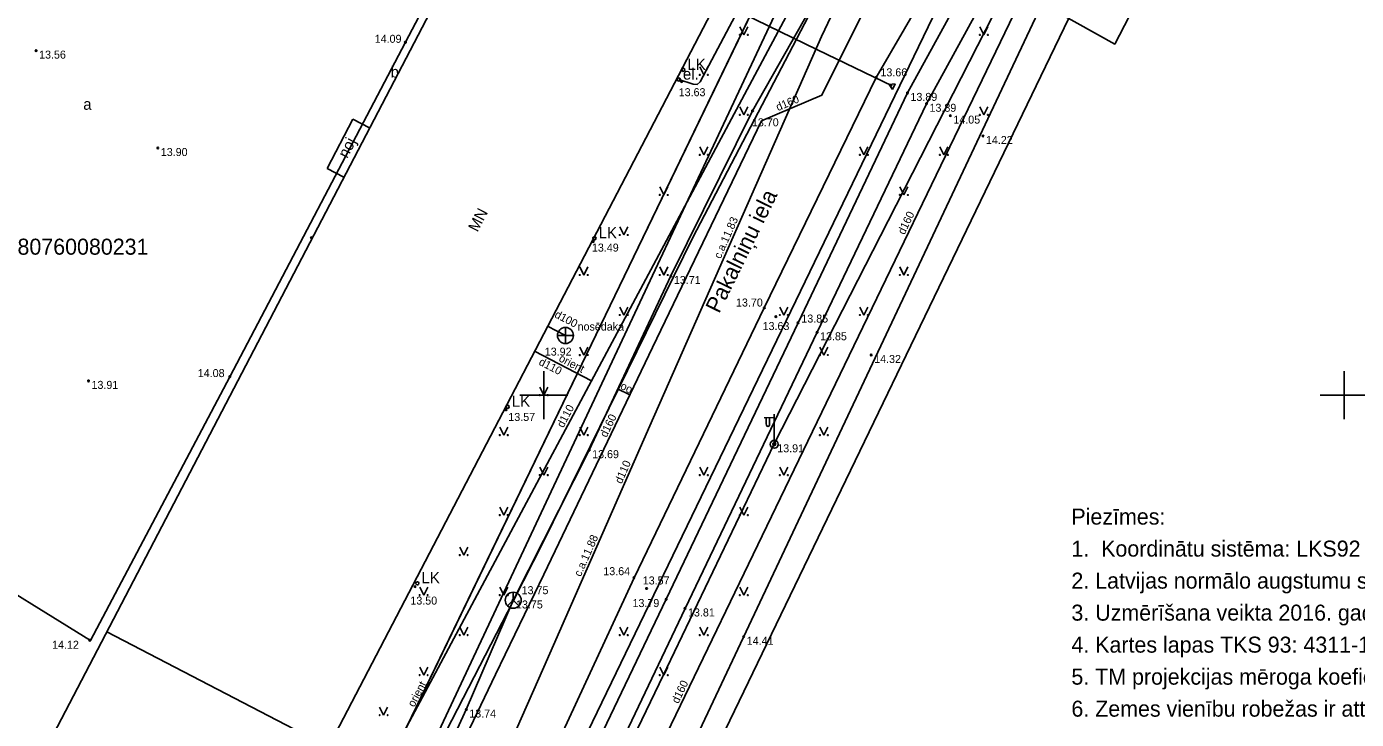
# Model space of a CAD drawing. Extents: x 503904 to 504094, y 304688 to 304960.
# Drawn here: x 503967.7 to 504050.8, y 304779.7 to 304823 of the extents above; entities that cross this region are included whole.
import ezdxf

# ---------------------------------------------------------------- set-up
doc = ezdxf.new("R2010")
doc.units = 0
for name, color, linetype in [('APGR_SARK_####_####_#', 7, 'Continuous'), ('APGS_ELEM_####_####_#', 7, 'Continuous'), ('APGS_VADP_ZSPR_####_#', 7, 'Continuous'), ('BUVE_BALK_####_####_#', 7, 'Continuous'), ('BUVE_EKAS_####_####_#', 7, 'Continuous'), ('BUVE_EKAS_RAKS_TKST_#', 7, 'Continuous'), ('CELI_CMAL_####_####_#', 7, 'Continuous'), ('CELI_CSEG_####_TKST_#', 7, 'Continuous'), ('CELI_IELA_####_TKST_#', 7, 'Continuous'), ('ELEK_ELEM_####_####_#', 7, 'Continuous'), ('ELEK_VADP_NEDR_####_#', 7, 'Continuous'), ('GAZE_VADP_VSP2_####_#', 7, 'Continuous'), ('GAZE_VADP_VSP2_TKST_#', 7, 'Continuous'), ('GEOD_ELEM_####_####_#', 7, 'Continuous'), ('LKAN_ELEM_####_####_#', 7, 'Continuous'), ('RAMI_PLAN_####_TKST_#', 7, 'Continuous'), ('RAMI_UZMR_####_####_#', 7, 'Continuous'), ('RELJ_AATZ_####_TKST_#', 7, 'Continuous'), ('RELJ_ELEM_####_####_#', 7, 'Continuous'), ('ROBZ_UZMR_####_####_#', 7, 'Continuous'), ('ROBZ_UZMR_####_TKST_#', 7, 'Continuous'), ('SAKK_ELEM_####_####_#', 7, 'Continuous'), ('SAKK_ELEM_####_TKST_#', 7, 'Continuous'), ('SAKK_IZVK_####_TKST_#', 7, 'Continuous'), ('SAKK_KKAN_####_####_#', 7, 'Continuous'), ('SAKT_VADP_KABE_####_#', 7, 'Continuous'), ('SKAN_ELEM_####_####_#', 7, 'Continuous'), ('SKAN_ELEM_PAST_TKST_#', 7, 'Continuous'), ('SKAN_VADP_PAST_####_#', 7, 'Continuous'), ('SKAN_VADP_PAST_TKST_#', 7, 'Continuous'), ('SKAN_VADP_SPDK_####_I', 7, 'Continuous'), ('SKAN_VADP_SPDK_TKST_I', 7, 'Continuous'), ('TERT_ELEM_####_####_#', 7, 'Continuous'), ('UDTK_VADP_UDEN_####_#', 7, 'Continuous'), ('UDTK_VADP_UDEN_TKST_#', 7, 'Continuous')]:
    doc.layers.add(name, color=color, linetype=linetype)

msp = doc.modelspace()

# ---------------------------------------------------------------- linework, layer by layer
at = {"layer": 'APGR_SARK_####_####_#'}
for p, q in [((504030.463, 304860.121), (503981.982, 304759.672)), ((504032.794, 304823.54), (503998.701, 304752.902))]:
    msp.add_line(p, q, dxfattribs=at)
at = {"layer": 'APGS_ELEM_####_####_#'}
for p, q in [((504014.404, 304798.589), (504013.769, 304798.584)), ((504013.904, 304798.585), (504013.904, 304798.193)), ((504014.114, 304798.587), (504014.114, 304798.193)), ((504014.404, 304796.922), (504014.404, 304798.805))]:
    msp.add_line(p, q, dxfattribs=at)
for radius in [0.25, 0.09]:
    msp.add_circle((504014.404, 304796.922), radius, dxfattribs=at)
msp.add_ellipse((504014.009, 304798.193), major_axis=(0, 0.151), ratio=0.695971, start_param=1.570796, end_param=4.712389, dxfattribs=at)
at = {"layer": 'APGS_VADP_ZSPR_####_#'}
for points in [[(504014.402, 304796.949), (504021.513, 304810.881), (504028.624, 304824.813), (504030.913, 304829.297), (504033.174, 304833.728), (504034.064, 304835.47), (504034.948, 304837.203)], [(503997.69, 304760.643), (503998.828, 304763.774), (503999.966, 304766.905), (504007.201, 304781.962), (504014.402, 304796.949)]]:
    msp.add_lwpolyline(points, dxfattribs=at)
at = {"layer": 'BUVE_BALK_####_####_#'}
for points in [[(503988.071, 304817.243), (503986.462, 304814.159)], [(503988.071, 304817.243), (503989.125, 304816.693)], [(503986.462, 304814.159), (503987.516, 304813.609)]]:
    msp.add_lwpolyline(points, dxfattribs=at)
at = {"layer": 'BUVE_EKAS_####_####_#'}
for p, q in [((504000.528, 304838.553), (503966.985, 304774.25)), ((503980.794, 304766.985), (504014.326, 304831.324)), ((503986.542, 304778.014), (503972.696, 304785.199))]:
    msp.add_line(p, q, dxfattribs=at)
at = {"layer": 'CELI_CMAL_####_####_#'}
msp.add_line((504013.046, 304817.755), (504026.066, 304840.762), dxfattribs=at)
for points in [[(503988.454, 304902.158), (503990.823, 304901.054), (503991.097, 304895.946), (503989.732, 304890.943), (503987.103, 304886.103), (503981.039, 304876.47), (503973.971, 304864.108), (503962.412, 304839.295), (503956.935, 304827.255), (503950.616, 304813.727), (503945.51, 304803.343), (503951.501, 304800.629), (503951.721, 304801.18), (503956.987, 304798.767), (503955.478, 304795.066), (503959.037, 304792.215), (503963.727, 304789.581), (503971.677, 304784.658)], [(503980.391, 304801.145), (503991.362, 304822.043), (504000.143, 304838.769)], [(503992.452, 304751.249), (503998.132, 304767.348), (504007.65, 304787.237), (504015.889, 304804.514), (504022.724, 304818.878), (504029.221, 304830.725)], [(504030.694, 304830.598), (504023.914, 304818.199), (504017.078, 304803.923), (504008.828, 304786.666), (503999.434, 304766.943), (503993.551, 304750.365)], [(503990.5, 304752.82), (503993.697, 304762.375), (503994.484, 304764.359), (503996.214, 304768.221), (504005.642, 304788.589), (504013.779, 304805.451), (504020.778, 304819.846), (504026.069, 304828.977)], [(504013.046, 304817.755), (504007.946, 304807.438), (504002.84, 304796.556), (503998.081, 304787.166), (503995.164, 304780.353), (503989.767, 304768.519), (503988.799, 304765.396), (503986.11, 304756.351)], [(503971.677, 304784.658), (503980.391, 304801.145)]]:
    msp.add_lwpolyline(points, dxfattribs=at)
at = {"layer": 'ELEK_ELEM_####_####_#'}
for points in [[(504021.782, 304819.089), (504021.581, 304819.409), (504021.956, 304819.449)], [(504021.956, 304819.449), (504021.782, 304819.089)]]:
    msp.add_lwpolyline(points, dxfattribs=at)
msp.add_circle((504008.434, 304819.711), 0.1, dxfattribs=at)
at = {"layer": 'ELEK_VADP_NEDR_####_#'}
for points in [[(504021.775, 304819.315), (504017.104, 304821.576), (504012.433, 304823.836), (504012.326, 304823.953), (504012.339, 304824.112), (504013.491, 304826.283), (504014.644, 304828.454), (504016.196, 304831.379), (504017.749, 304834.304), (504019.433, 304837.477), (504021.118, 304840.651), (504023.847, 304845.791), (504025.258, 304848.45), (504028.54, 304854.632), (504031.821, 304860.814), (504022.135, 304867.596), (504012.45, 304874.378)], [(504014.517, 304828.507), (504012.149, 304824.043), (504009.782, 304819.579), (504009.585, 304819.412), (504009.326, 304819.425), (504008.434, 304819.711)]]:
    msp.add_lwpolyline(points, dxfattribs=at)
at = {"layer": 'GAZE_VADP_VSP2_####_#'}
msp.add_lwpolyline([(504042.754, 304870.726), (504040.842, 304866.35), (504038.93, 304861.973), (504035.12, 304854.33), (504031.31, 304846.687), (504029.002, 304842.057), (504026.694, 304837.426), (504024.595, 304833.216), (504022.496, 304829.005), (504019.148, 304822.29), (504017.375, 304818.733), (504013.61, 304817.132), (504006.805, 304802.964), (504000, 304788.796), (503996.994, 304782.538), (503993.988, 304776.279), (503986.861, 304755.747)], dxfattribs=at)
at = {"layer": 'GEOD_ELEM_####_####_#'}
for p, q in [((504000, 304801.5), (504000, 304800)), ((504050, 304801.5), (504050, 304800)), ((503998.5, 304800), (504000, 304800)), ((504000, 304800), (504000, 304798.5)), ((504000, 304800), (504001.5, 304800)), ((504048.5, 304800), (504050, 304800)), ((504050, 304800), (504050, 304798.5)), ((504050, 304800), (504051.5, 304800))]:
    msp.add_line(p, q, dxfattribs=at)
at = {"layer": 'LKAN_ELEM_####_####_#'}
for centre in [(504008.717, 304820.318), (504003.169, 304809.791), (503997.749, 304799.265), (503992.105, 304788.24)]:
    msp.add_circle(centre, 0.1, dxfattribs=at)
at = {"layer": 'RAMI_UZMR_####_####_#'}
msp.add_lwpolyline([(503923.253, 304801.015), (503981.982, 304759.672), (503995.48, 304748.813), (504027.75, 304817.255), (504060.02, 304885.696), (504048.875, 304885.773), (504036.803, 304888.853), (503994.536, 304908.303), (503981.123, 304894.75), (503978.518, 304892.436), (503950.886, 304846.726), (503923.253, 304801.015)], dxfattribs=at)
at = {"layer": 'RELJ_ELEM_####_####_#'}
for centre in [(503968.288, 304821.519), (503991.362, 304822.043), (504020.778, 304819.846), (504008.62, 304819.584), (504022.724, 304818.878), (504023.914, 304818.199), (504013.046, 304817.755), (504025.406, 304817.459), (504027.44, 304816.183), (503975.891, 304815.433), (503985.486, 304809.827), (504003.088, 304809.591), (504007.946, 304807.438), (504013.779, 304805.451), (504014.502, 304804.898), (504015.889, 304804.514), (504017.078, 304803.923), (504020.458, 304802.504), (503971.562, 304800.885), (503980.391, 304801.145), (503997.64, 304799.08), (504002.84, 304796.556), (504005.642, 304788.589), (503991.954, 304788.033), (504006.424, 304787.913), (503998.081, 304787.166), (504007.65, 304787.237), (504008.828, 304786.666), (503971.641, 304784.68), (504012.496, 304784.899), (503995.164, 304780.353)]:
    msp.add_circle(centre, 0.05, dxfattribs=at)
at = {"layer": 'ROBZ_UZMR_####_####_#'}
msp.add_lwpolyline([(503923.29, 304801.044), (503978.518, 304892.436), (503981.123, 304894.75), (504030.463, 304860.121), (503981.982, 304759.672)], close=True, dxfattribs=at)
msp.add_lwpolyline([(503976.684, 304743.679), (503981.982, 304759.672), (504030.463, 304860.121), (504048.85, 304847.4), (504035.67, 304821.93), (504026.069, 304827.305), (503995.067, 304763.071), (503986.854, 304740.353)], dxfattribs=at)
at = {"layer": 'SAKK_ELEM_####_####_#'}
msp.add_line((503998.095, 304787.182), (503998.449, 304786.828), dxfattribs=at)
msp.add_lwpolyline([(503998.095, 304787.682), (503998.095, 304787.182), (503997.741, 304786.828)], dxfattribs=at)
msp.add_circle((503998.095, 304787.182), 0.5, dxfattribs=at)
at = {"layer": 'SAKK_IZVK_####_TKST_#'}
msp.add_line((504004.653, 304800.369), (504005.344, 304800.035), dxfattribs=at)
at = {"layer": 'SAKK_KKAN_####_####_#'}
msp.add_lwpolyline([(504039.007, 304870.064), (504036.678, 304863.872), (504034.349, 304857.68), (504031.408, 304852.312), (504030.269, 304850.237), (504027.088, 304844.191), (504022.232, 304834.693), (504020.138, 304830.591), (504009.306, 304809.848), (504000, 304790.89), (503998.089, 304787.127), (503992.169, 304775.655), (503986.248, 304764.183), (503984.196, 304757.891)], dxfattribs=at)
at = {"layer": 'SAKT_VADP_KABE_####_#'}
msp.add_lwpolyline([(503984.36, 304757.759), (503986.696, 304764.614), (504000.633, 304794.323), (504014.571, 304824.033), (504017.941, 304829.488), (504018.377, 304830.312), (504025.72, 304844.17), (504033.498, 304858.852), (504046.129, 304856.235)], dxfattribs=at)
at = {"layer": 'SKAN_ELEM_####_####_#'}
for p, q in [((504001.356, 304803.22), (504001.356, 304804.22)), ((504000.856, 304803.72), (504001.856, 304803.72))]:
    msp.add_line(p, q, dxfattribs=at)
msp.add_circle((504001.356, 304803.72), 0.5, dxfattribs=at)
at = {"layer": 'SKAN_VADP_PAST_####_#'}
msp.add_lwpolyline([(504001.356, 304803.72), (504000.242, 304804.301)], dxfattribs=at)
at = {"layer": 'SKAN_VADP_SPDK_####_I'}
msp.add_lwpolyline([(503989.264, 304753.814), (503995.932, 304773.743), (504000, 304782.989), (504006.638, 304798.076), (504017.345, 304822.408), (504018.739, 304825.349), (504022.372, 304833.011), (504023.783, 304835.985)], dxfattribs=at)
at = {"layer": 'TERT_ELEM_####_####_#'}
for p, q in [((504012.25, 304823), (504012.5, 304822.5)), ((504012.5, 304822.5), (504012.75, 304823)), ((504027.25, 304823), (504027.5, 304822.5)), ((504027.5, 304822.5), (504027.75, 304823)), ((504009.75, 304820.5), (504010, 304820)), ((504010, 304820), (504010.25, 304820.5)), ((504012.25, 304818), (504012.5, 304817.5)), ((504012.5, 304817.5), (504012.75, 304818)), ((504027.25, 304818), (504027.5, 304817.5)), ((504027.5, 304817.5), (504027.75, 304818)), ((504009.75, 304815.5), (504010, 304815)), ((504010, 304815), (504010.25, 304815.5)), ((504019.75, 304815.5), (504020, 304815)), ((504020, 304815), (504020.25, 304815.5)), ((504024.75, 304815.5), (504025, 304815)), ((504025, 304815), (504025.25, 304815.5)), ((504007.25, 304813), (504007.5, 304812.5)), ((504007.5, 304812.5), (504007.75, 304813)), ((504022.25, 304813), (504022.5, 304812.5)), ((504022.5, 304812.5), (504022.75, 304813)), ((504004.75, 304810.5), (504005, 304810)), ((504005, 304810), (504005.25, 304810.5)), ((504002.25, 304808), (504002.5, 304807.5)), ((504002.5, 304807.5), (504002.75, 304808)), ((504007.25, 304808), (504007.5, 304807.5)), ((504007.5, 304807.5), (504007.75, 304808)), ((504022.25, 304808), (504022.5, 304807.5)), ((504022.5, 304807.5), (504022.75, 304808)), ((504004.75, 304805.5), (504005, 304805)), ((504005, 304805), (504005.25, 304805.5)), ((504014.75, 304805.5), (504015, 304805)), ((504015, 304805), (504015.25, 304805.5)), ((504019.75, 304805.5), (504020, 304805)), ((504020, 304805), (504020.25, 304805.5)), ((504002.25, 304803), (504002.5, 304802.5)), ((504002.5, 304802.5), (504002.75, 304803)), ((504017.25, 304803), (504017.5, 304802.5)), ((504017.5, 304802.5), (504017.75, 304803)), ((503999.75, 304800.5), (504000, 304800)), ((504000, 304800), (504000.25, 304800.5)), ((503997.25, 304798), (503997.5, 304797.5)), ((503997.5, 304797.5), (503997.75, 304798)), ((504002.25, 304798), (504002.5, 304797.5)), ((504002.5, 304797.5), (504002.75, 304798)), ((504017.25, 304798), (504017.5, 304797.5)), ((504017.5, 304797.5), (504017.75, 304798)), ((503999.75, 304795.5), (504000, 304795)), ((504000, 304795), (504000.25, 304795.5)), ((504009.75, 304795.5), (504010, 304795)), ((504010, 304795), (504010.25, 304795.5)), ((504014.75, 304795.5), (504015, 304795)), ((504015, 304795), (504015.25, 304795.5)), ((503997.25, 304793), (503997.5, 304792.5)), ((503997.5, 304792.5), (503997.75, 304793)), ((504012.25, 304793), (504012.5, 304792.5)), ((504012.5, 304792.5), (504012.75, 304793)), ((503994.75, 304790.5), (503995, 304790)), ((503995, 304790), (503995.25, 304790.5)), ((503992.25, 304788), (503992.5, 304787.5)), ((503992.5, 304787.5), (503992.75, 304788)), ((503997.25, 304788), (503997.5, 304787.5)), ((503997.5, 304787.5), (503997.75, 304788)), ((504012.25, 304788), (504012.5, 304787.5)), ((504012.5, 304787.5), (504012.75, 304788)), ((503994.75, 304785.5), (503995, 304785)), ((503995, 304785), (503995.25, 304785.5)), ((504004.75, 304785.5), (504005, 304785)), ((504005, 304785), (504005.25, 304785.5)), ((504009.75, 304785.5), (504010, 304785)), ((504010, 304785), (504010.25, 304785.5)), ((503992.25, 304783), (503992.5, 304782.5)), ((503992.5, 304782.5), (503992.75, 304783)), ((504007.25, 304783), (504007.5, 304782.5)), ((504007.5, 304782.5), (504007.75, 304783)), ((503989.75, 304780.5), (503990, 304780)), ((503990, 304780), (503990.25, 304780.5))]:
    msp.add_line(p, q, dxfattribs=at)
for centre, radius in [((504012.25, 304822.5), 0.028), ((504012.75, 304822.5), 0.0263), ((504027.25, 304822.5), 0.028), ((504027.75, 304822.5), 0.0263), ((504009.75, 304820), 0.028), ((504010.25, 304820), 0.0263), ((504012.25, 304817.5), 0.028), ((504012.75, 304817.5), 0.0263), ((504027.25, 304817.5), 0.028), ((504027.75, 304817.5), 0.0263), ((504009.75, 304815), 0.028), ((504010.25, 304815), 0.0263), ((504019.75, 304815), 0.028), ((504020.25, 304815), 0.0263), ((504024.75, 304815), 0.028), ((504025.25, 304815), 0.0263), ((504007.25, 304812.5), 0.028), ((504007.75, 304812.5), 0.0263), ((504022.25, 304812.5), 0.028), ((504022.75, 304812.5), 0.0263), ((504004.75, 304810), 0.028), ((504005.25, 304810), 0.0263), ((504002.25, 304807.5), 0.028), ((504002.75, 304807.5), 0.0263), ((504007.25, 304807.5), 0.028), ((504007.75, 304807.5), 0.0263), ((504022.25, 304807.5), 0.028), ((504022.75, 304807.5), 0.0263), ((504004.75, 304805), 0.028), ((504005.25, 304805), 0.0263), ((504014.75, 304805), 0.028), ((504015.25, 304805), 0.0263), ((504019.75, 304805), 0.028), ((504020.25, 304805), 0.0263), ((504002.25, 304802.5), 0.028), ((504002.75, 304802.5), 0.0263), ((504017.25, 304802.5), 0.028), ((504017.75, 304802.5), 0.0263), ((503999.75, 304800), 0.028), ((504000.25, 304800), 0.0263), ((503997.25, 304797.5), 0.028), ((503997.75, 304797.5), 0.0263), ((504002.25, 304797.5), 0.028), ((504002.75, 304797.5), 0.0263), ((504017.25, 304797.5), 0.028), ((504017.75, 304797.5), 0.0263), ((503999.75, 304795), 0.028), ((504000.25, 304795), 0.0263), ((504009.75, 304795), 0.028), ((504010.25, 304795), 0.0263), ((504014.75, 304795), 0.028), ((504015.25, 304795), 0.0263), ((503997.25, 304792.5), 0.028), ((503997.75, 304792.5), 0.0263), ((504012.25, 304792.5), 0.028), ((504012.75, 304792.5), 0.0263), ((503994.75, 304790), 0.028), ((503995.25, 304790), 0.0263), ((503992.25, 304787.5), 0.028), ((503992.75, 304787.5), 0.0263), ((503997.25, 304787.5), 0.028), ((503997.75, 304787.5), 0.0263), ((504012.25, 304787.5), 0.028), ((504012.75, 304787.5), 0.0263), ((503994.75, 304785), 0.028), ((503995.25, 304785), 0.0263), ((504004.75, 304785), 0.028), ((504005.25, 304785), 0.0263), ((504009.75, 304785), 0.028), ((504010.25, 304785), 0.0263), ((503992.25, 304782.5), 0.028), ((503992.75, 304782.5), 0.0263), ((504007.25, 304782.5), 0.028), ((504007.75, 304782.5), 0.0263), ((503989.75, 304780), 0.028), ((503990.25, 304780), 0.0263)]:
    msp.add_circle(centre, radius, dxfattribs=at)
at = {"layer": 'UDTK_VADP_UDEN_####_#'}
for points in [[(504052.599, 304884.688), (504054.563, 304874.709), (504047.684, 304860.837), (504037.414, 304840.144), (504031.385, 304827.996), (504014.788, 304793.579), (504000, 304762.914), (503998.944, 304760.723), (503997.887, 304758.532), (503994.035, 304750.096), (503993.994, 304750.008)], [(504035.876, 304862.497), (503981.246, 304760.191)], [(504002.977, 304800.887), (503999.427, 304802.737)]]:
    msp.add_lwpolyline(points, dxfattribs=at)

# ---------------------------------------------------------------- texts
at = {"layer": 'BUVE_EKAS_RAKS_TKST_#'}
for s, rotation, p in [('noj', 62.45166, (503987.725, 304814.745)), ('MN', 62.47252, (503995.862, 304810.141))]:
    msp.add_text(s, height=0.7, rotation=rotation, dxfattribs=at).set_placement(p)
at = {"layer": 'CELI_CSEG_####_TKST_#'}
for s, p in [('b', (503990.431, 304819.837)), ('a', (503971.232, 304817.823))]:
    msp.add_text(s, height=0.7, dxfattribs=at).set_placement(p)
at = {"layer": 'CELI_IELA_####_TKST_#'}
msp.add_text('Pakalniņu iela', height=1, rotation=63.86421, dxfattribs=at).set_placement((504010.957, 304805.048))
at = {"layer": 'ELEK_ELEM_####_####_#'}
msp.add_text(' el.', height=0.7, dxfattribs=at).set_placement((504008.434, 304819.711))
at = {"layer": 'GAZE_VADP_VSP2_TKST_#'}
for rotation, p in [(23.03677, (504014.636, 304817.731)), (64.34467, (504003.925, 304797.314))]:
    msp.add_text('d160', height=0.5, rotation=rotation, dxfattribs=at).set_placement(p)
at = {"layer": 'LKAN_ELEM_####_####_#'}
for p in [(504008.717, 304820.318), (504003.169, 304809.791), (503997.749, 304799.265), (503992.105, 304788.24)]:
    msp.add_text(' LK', height=0.7, dxfattribs=at).set_placement(p)
at = {"layer": 'RAMI_PLAN_####_TKST_#'}
for s, p in [('Piezīmes:', (504032.965, 304791.905)), ('1.  Koordinātu sistēma: LKS92 TM', (504032.965, 304789.905)), ('2. Latvijas normālo augstumu sistēma (LAS-2000,5)', (504032.965, 304787.905)), ('3. Uzmērīšana veikta 2016. gada 9. jūnijā', (504032.965, 304785.905)), ('4. Kartes lapas TKS 93: 4311-11-55.3-807600, 4311-11-54.4-807600', (504032.965, 304783.905)), ('5. TM projekcijas mēroga koeficents 0.999600', (504032.965, 304781.905)), ('6. Zemes vienību robežas ir attēlotas atbilstoši zemes ', (504032.965, 304779.905))]:
    msp.add_text(s, height=1, rotation=360, dxfattribs=at).set_placement(p)
at = {"layer": 'RELJ_AATZ_####_TKST_#'}
for s, p in [(' 14.09', (503989.255, 304822.008)), (' 13.56', (503968.288, 304821.019)), (' 13.66', (504020.848, 304819.912)), (' 13.63', (504008.245, 304818.67)), (' 13.89', (504022.724, 304818.378)), (' 13.89', (504023.914, 304817.699)), (' 14.05', (504025.406, 304816.959)), (' 13.70', (504012.819, 304816.79)), (' 14.22', (504027.44, 304815.683)), (' 13.90', (503975.891, 304814.933)), (' 13.49', (504002.825, 304808.963)), (' 13.71', (504007.946, 304806.938)), (' 13.70', (504011.825, 304805.53)), (' 13.85', (504015.907, 304804.528)), (' 13.63', (504013.488, 304804.06)), (' 13.85', (504017.078, 304803.423)), (' 14.32', (504020.458, 304802.004)), (' 14.08', (503978.203, 304801.122)), (' 13.91', (503971.562, 304800.385)), (' 13.57', (503997.602, 304798.381)), (' 13.91', (504014.404, 304796.422)), (' 13.69', (504002.84, 304796.056)), (' 13.64', (504003.536, 304788.746)), (' 13.57', (504006, 304788.166)), (' 13.50', (503991.484, 304786.909)), (' 13.75', (503998.081, 304786.666)), (' 13.79', (504005.36, 304786.753)), (' 13.81', (504008.828, 304786.166)), (' 14.12', (503969.101, 304784.149)), (' 14.41', (504012.496, 304784.399)), (' 13.74', (503995.164, 304779.853))]:
    msp.add_text(s, height=0.5, dxfattribs=at).set_placement(p)
at = {"layer": 'ROBZ_UZMR_####_TKST_#'}
msp.add_text('80760080231', height=1, dxfattribs=at).set_placement((503967.125, 304808.769))
at = {"layer": 'SAKK_ELEM_####_TKST_#'}
msp.add_text('13.75', height=0.5, dxfattribs=at).set_placement((503998.619, 304787.558))
at = {"layer": 'SAKK_IZVK_####_TKST_#'}
msp.add_text('oo', height=0.5, rotation=334.24935, dxfattribs=at).set_placement((504004.738, 304800.404))
at = {"layer": 'SKAN_ELEM_PAST_TKST_#'}
for s, p in [('nosēdaka', (504002.117, 304804.03)), ('13.92', (504000.065, 304802.463))]:
    msp.add_text(s, height=0.5, dxfattribs=at).set_placement(p)
at = {"layer": 'SKAN_VADP_PAST_TKST_#'}
msp.add_text('d100', height=0.5, rotation=332.47252, dxfattribs=at).set_placement((504000.632, 304804.88))
at = {"layer": 'SKAN_VADP_SPDK_TKST_I'}
for s, p in [('c.a.11.83', (504011.051, 304808.476)), ('d110', (504004.865, 304794.418)), ('c.a.11.88', (504002.312, 304788.615))]:
    msp.add_text(s, height=0.5, rotation=66.25023, dxfattribs=at).set_placement(p)
at = {"layer": 'UDTK_VADP_UDEN_TKST_#'}
for s, rotation, p in [('d160', 64.25499, (504022.532, 304809.982)), ('orient', 332.47252, (504000.896, 304802.141)), ('d110', 332.47252, (503999.647, 304801.919)), ('d110', 61.89854, (504001.222, 304797.918)), ('orient', 61.89854, (503991.903, 304780.467)), ('d160', 64.25499, (504008.404, 304780.686))]:
    msp.add_text(s, height=0.5, rotation=rotation, dxfattribs=at).set_placement(p)

doc.saveas('drawing.dxf')
